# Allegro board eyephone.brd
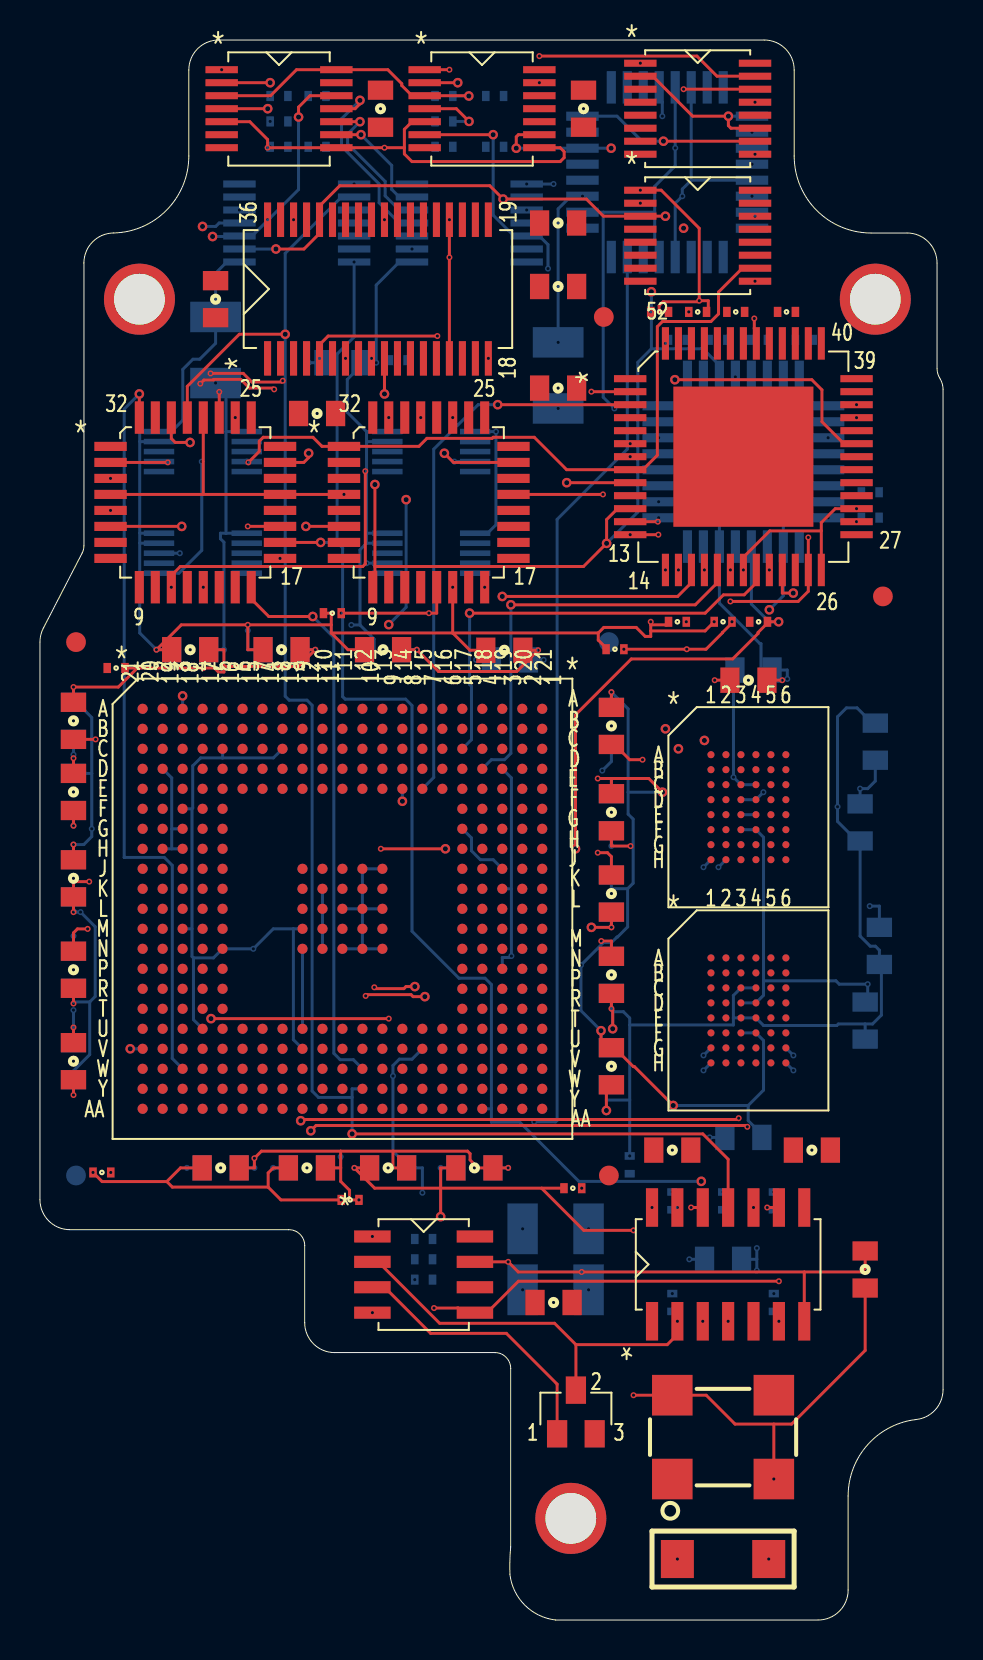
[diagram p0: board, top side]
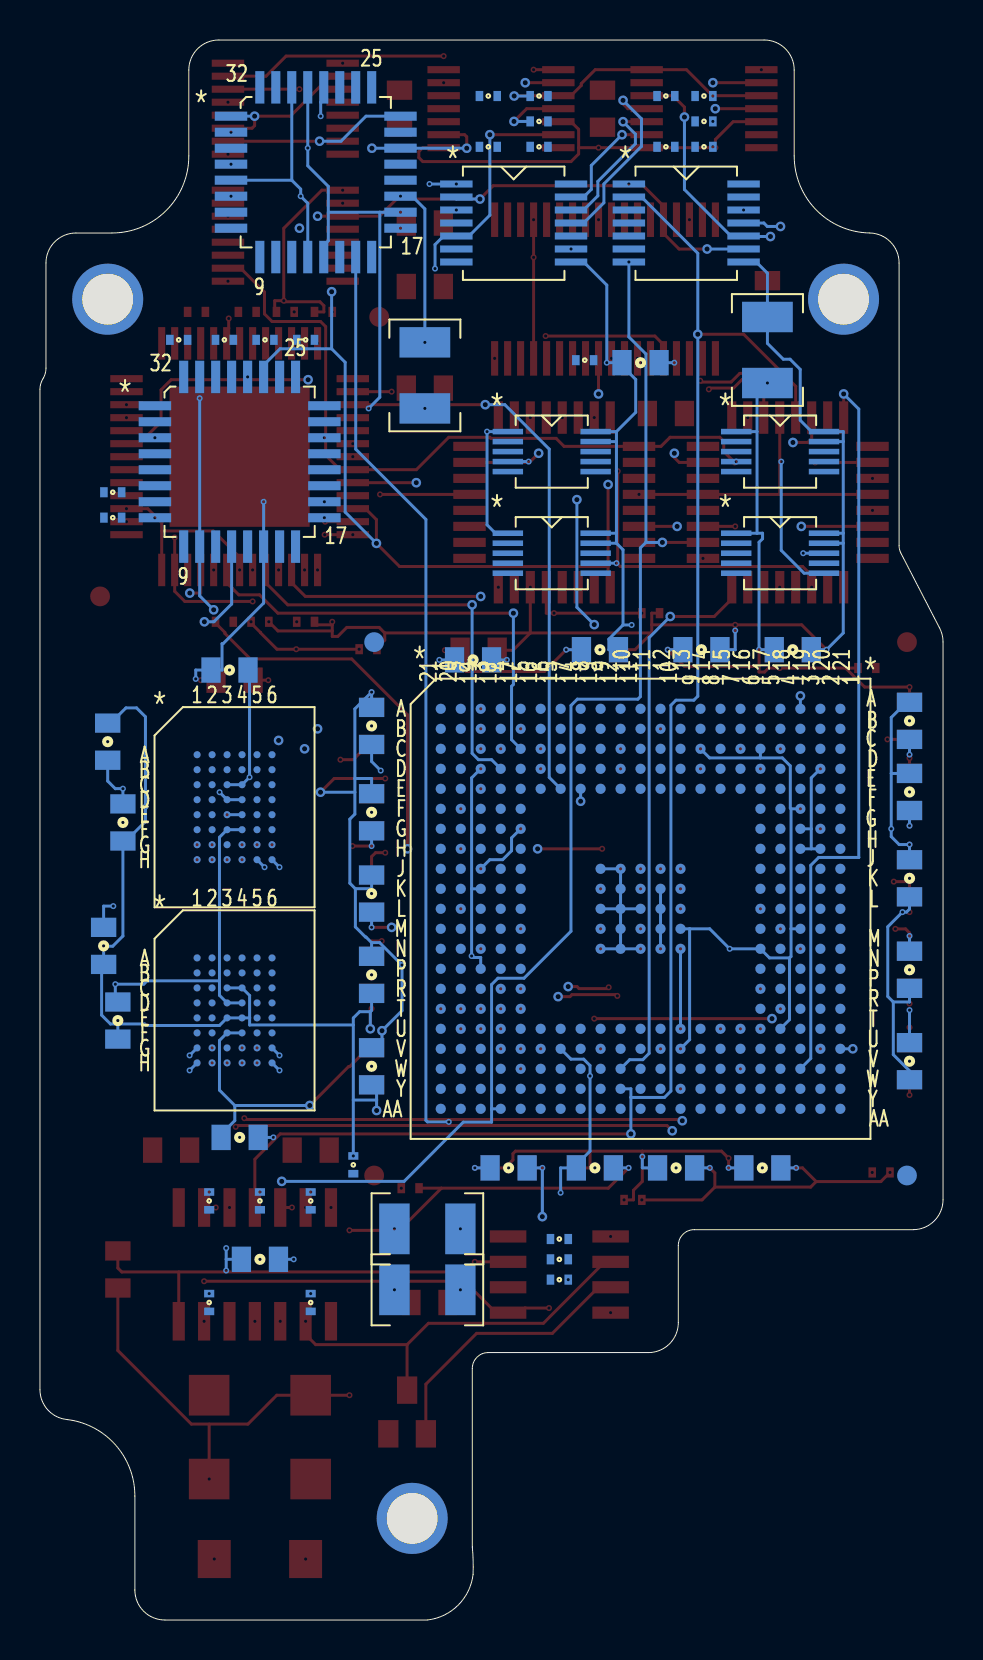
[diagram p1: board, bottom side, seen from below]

Outline 45.2 x 79 mm; copper layers: TOP, GND, VCC, BOTTOM. Coordinates in mm from the lower left corner of the outline.
Outline path: 0,48.9 0,21.02 arc(0.44,19.96) 1.5,19.52 12.46,19.52 arc(13.02,19.28) 13.25,18.73 13.25,14.87 arc(13.69,13.81) 14.75,13.37 22.77,13.37 arc(23.33,13.14) 23.56,12.58 23.56,3.65 arc(23.52,2.97) 23.52,2.29 arc(24.27,0.74) 25.81,0 38.95,0 arc(40.01,0.44) 40.45,1.5 40.45,6.2 arc(41.43,8.77) 43.87,10.03 arc(44.82,10.52) 45.2,11.52 45.2,61.54 arc(45.16,61.81) 45.05,62.06 arc(44.94,62.32) 44.9,62.59 44.9,67.85 arc(44.46,68.91) 43.4,69.35 41.6,69.35 arc(38.88,70.48) 37.75,73.2 37.75,77.5 arc(37.31,78.56) 36.25,79 8.95,79 arc(7.89,78.56) 7.45,77.5 7.45,73.2 arc(6.35,70.5) 3.67,69.35 arc(2.63,68.9) 2.2,67.85 2.2,53.71 arc(2.18,53.52) 2.11,53.35 0.17,49.59 arc(0.04,49.26) 0,48.9

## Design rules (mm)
net group DP1: nets PECL1_N PECL1_P
net group DP2: nets PECL2_N PECL2_P
net group ADDR_BUS: nets ADDR0 ADDR1 ADDR2 ADDR3 ADDR4 ADDR5 ADDR6 ADDR7 ADDR8 ADDR9 ADDR10

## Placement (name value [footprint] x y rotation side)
C1  120PF  [SMC0805]  28.6 32.26 90 top
C2  120PF  [SMC0805]  1.68 44.96 90 top
C3  120PF  [SMC0805]  1.68 41.4 90 top
C4  120PF  [SMC0805]  1.68 37.08 90 top
C5  120PF  [SMC0805]  1.68 27.94 90 top
C6  120PF  [SMC0805]  1.68 32.51 90 top
C7  120PF  [SMC0805]  17.17 48.51 0 top
C8  120PF  [SMC0805]  28.6 44.7 90 top
C9  120PF  [SMC0805]  28.6 40.39 90 top
C10  120PF  [SMC0805]  28.6 36.32 90 top
C11  120PF  [SMC0805]  28.6 27.69 90 top
C12  120PF  [SMC0805]  23.24 48.49 0 top
C13  120PF  [SMC0805]  9.04 22.61 0 top
C14  120PF  [SMC0805]  13.36 22.61 0 top
C15  120PF  [SMC0805]  17.43 22.61 0 top
C16  120PF  [SMC0805]  21.74 22.61 0 top
C17  120PF  [SMC0805]  35.46 46.99 0 top
C18  120PF  [SMC0805]  41.3 17.53 90 top
C19  120PF  [SMC0805]  7.52 48.51 0 top
C20  120PF  [SMC0805]  12.09 48.51 0 top
C21  120PF  [SMC0805]  1.68 37.08 90 bottom
C22  120PF  [SMC0805]  1.68 32.51 90 bottom
C23  120PF  [SMC0805]  12.09 48.51 0 bottom
C24  120PF  [SMC0805]  1.68 27.94 90 bottom
C25  120PF  [SMC0805]  9.04 22.61 0 bottom
C26  120PF  [SMC0805]  17.17 48.51 0 bottom
C27  120PF  [SMC0805]  23.52 48.01 0 bottom
C28  120PF  [SMC0805]  28.6 44.7 90 bottom
C29  120PF  [SMC0805]  28.6 40.39 90 bottom
C30  120PF  [SMC0805]  28.6 36.32 90 bottom
C31  120PF  [SMC0805]  28.6 32.26 90 bottom
C32  120PF  [SMC0805]  7.52 48.51 0 bottom
C33  120PF  [SMC0805]  17.43 22.61 0 bottom
C34  120PF  [SMC0805]  13.36 22.61 0 bottom
C35  120PF  [SMC0805]  21.74 22.61 0 bottom
C36  120PF  [SMC0805]  28.6 27.69 90 bottom
C37  120PF  [SMC0805]  35.21 24.13 0 bottom
C38  120PF  [SMC0805]  35.71 47.5 0 bottom
C39  120PF  [SMC0805]  1.68 41.4 90 bottom
C40  120PF  [SMC0805]  1.68 44.96 90 bottom
C41  10uF  [1210RF]  8.79 63.5 270 bottom
C42  10uF  [1210RF]  25.93 62.23 270 bottom
C43  10uF  [1210RF]  25.81 16.51 180 bottom
C44  10uF  [1210RF]  25.81 19.56 180 bottom
C45  120PF  [SMC0805]  15.14 62.87 180 bottom
C46  120PF  [SMC0805]  41.3 29.97 90 bottom
C47  120PF  [SMC0805]  42.01 33.71 90 bottom
C48  120PF  [SMC0805]  41.81 43.92 270 bottom
C49  120PF  [SMC0805]  41.05 39.88 90 bottom
C50  120PF  [SMC0805]  34.19 18.03 180 bottom
C51  .1UF  [R_0402]  3.81 47.6 0 top
C52  .1UF  [R_0402]  14.63 50.34 0 top
C53  .1UF  [R_0402]  3.1 22.38 0 top
C54  .1UF  [R_0402]  28.78 48.54 0 top
C55  .1UF  [R_0402]  15.52 21.01 0 top
C56  .1UF  [R_0402]  26.67 21.59 0 top
C57  .1UF  [R_0402]  31.01 65.41 0 top
C58  .1UF  [R_0402]  32.92 65.41 0 top
C59  .1UF  [R_0402]  34.19 49.91 0 top
C60  .1UF  [R_0402]  31.9 49.91 0 top
C61  120PF  [SMC0805]  25.93 66.67 0 top
C62  120PF  [SMC0805]  38.63 23.5 0 top
C63  120PF  [SMC0805]  8.79 66.04 90 top
C64  120PF  [SMC0805]  25.93 69.85 0 top
C65  120PF  [SMC0805]  17.04 75.56 90 top
C66  120PF  [SMC0805]  27.2 75.56 90 top
C67  120PF  [SMC0805]  31.65 23.5 0 top
C68  120PF  [SMC0805]  25.71 15.88 0 top
C69  120PF  [SMC0805]  25.93 61.59 0 top
C70  120PF  [SMC0805]  13.87 60.33 0 top
D1  -  [SOT23_132]  26.82 10.41 0 top
D2  V  [SMF1806]  34.19 3.05 180 top
NOREF  -  [unnamed]  26.57 5.08 0 top
NOREF#2  -  [unnamed]  4.98 66.04 0 top
NOREF#3  -  [unnamed]  41.81 66.04 0 top
R1  10K  [R_0402]  34.82 65.41 0 top
R2  10K  [R_0402]  37.36 65.41 0 top
R3  10K  [R_0402]  31.9 64.01 180 bottom
R4  10K  [R_0402]  33.94 64.01 180 bottom
R5  10K  [R_0402]  35.97 64.01 180 bottom
R6  10K  [R_0402]  38.25 64.01 180 bottom
R7  10K  [R_0402]  17.93 62.99 180 bottom
R8  10K  [R_0402]  22.76 73.66 180 bottom
R9  10K  [R_0402]  13.87 76.2 180 bottom
R10  10K  [R_0402]  13.87 73.66 180 bottom
R11  10K  [R_0402]  35.97 49.91 0 top
R12  10K  [R_0402]  22.76 76.2 180 bottom
R13  10K  [R_0402]  20.22 76.2 180 bottom
R14  10K  [R_0402]  11.96 73.66 180 bottom
R15  10K  [R_0402]  11.96 76.2 180 bottom
R16  10K  [R_0402]  11.96 74.93 180 bottom
R17  10K  [R_0402]  20.22 74.93 180 bottom
R18  10K  [R_0402]  20.22 73.66 180 bottom
R19  10K  [R_0402]  41.56 56.39 180 bottom
R20  10K  [R_0402]  19.2 18.03 180 bottom
R21  10K  [R_0402]  19.2 19.05 180 bottom
R22  10K  [R_0402]  19.2 17.02 180 bottom
R23  10K  [R_0402]  41.56 55.12 180 bottom
R24  10K  [R_0402]  29.52 22.76 90 bottom
R25  10K  [R_0402]  31.65 20.95 90 bottom
R26  10K  [R_0402]  36.73 15.88 90 bottom
R27  10K  [R_0402]  34.19 20.95 90 bottom
R28  10K  [R_0402]  31.65 15.88 90 bottom
R29  10K  [R_0402]  36.73 20.95 90 bottom
U1  -  [TSSOP14_26CC_BD4-4MM]  11.96 75.56 0 top
U2  -  [TSSOP14_26CC_BD4-4MM]  22.12 75.56 0 top
U3  -  [TSSOP14_26CC_BD4-4MM]  12.85 69.85 180 bottom
U4  -  [TSSOP14_26CC_BD4-4MM]  21.49 69.85 180 bottom
U5  -  [BGA345_BD23X23MM]  15.14 35.56 0 top
U6  -  [BGA345_BD23X23MM]  15.14 35.56 180 bottom
U7  -  [BGA48_BD7-5X9-5MM]  35.46 40.64 0 top
U8  -  [BGA48_BD7-5X9-5MM]  35.46 30.48 0 top
U9  -  [BGA48_BD7-5X9-5MM]  35.46 40.64 180 bottom
U10  -  [BGA48_BD7-5X9-5MM]  35.46 30.48 180 bottom
U11  -  [SO14NB]  34.44 17.78 90 top
U12  -  [TQFP52_BD10X10MM_THERM]  35.21 58.17 0 top
U13  -  [SSOP36_26CC_BD5-3MM]  16.92 66.55 90 top
U14  -  [SO8NB_V2]  19.2 17.27 0 top
U15  -  [TSSOP16_26CC_BD4-4MM]  32.92 69.22 0 top
U16  -  [TSSOP16_26CC_BD4-4MM]  32.92 75.56 0 top
U17  -  [TQFP32_32CC_BD7X7MM]  7.77 55.88 0 top
U18  -  [TQFP32_32CC_BD7X7MM]  19.46 55.88 0 top
U19  -  [TQFP32_32CC_BD7X7MM]  35.21 57.91 180 bottom
U20  -  [TQFP32_32CC_BD7X7MM]  31.4 72.39 180 bottom
U21  -  [MSOP10_20CC_BD3MM]  8.15 58.42 180 bottom
U22  -  [MSOP10_20CC_BD3MM]  8.15 53.34 180 bottom
U23  -  [MSOP10_20CC_BD3MM]  19.58 58.42 180 bottom
U24  -  [MSOP10_20CC_BD3MM]  19.58 53.34 180 bottom
Y1  -  [4CERAMIC]  34.19 9.14 90 top

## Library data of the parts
C1-C40 C45-C50 C61-C70 = CAP: Tolerance: 5%; alternate symbols: (VSMC0805L,VSMC0805R,VSMC0805B,SMC0805); part number: CAP_805-120PF,5%,50V,805; signal model: capacitor120pF; tolerance: 5%
C41-C44 = CAP: Tolerance: +80-20%; User Part Number: 110-1925-01; alternate symbols: (1210RF_WVI_10P;1210RF_V12P;1210WS;1210WS_WVI_10P); part number: CAP_SMT1210-110-1925-01,10UF,+80-20%,16V; tolerance: +80-20%
C51-C60 = CAP: alternate symbols: (VSMC0603L,VSMC0603R,VSMC0603B,SMC0603); part number: CAP_402-.1UF,&10%,80%,6.3V; signal model: capacitor0pF; tolerance: 10%
D1 = RCNET: User Part Number: 120-3831-01; Tolerance: 10%; part number: RCNET_SOT23-120-3831-01,CTXS03,50,46.4,50,150PF,10%; tolerance: 10%
D2 = BEAD_1806: Tolerance: T; User Part Number: P; part number: BEAD_1806_SMF1806-FBMH4516,TAIYO_FERRITE_BEAD,6A
R1-R29 = RES: alternate symbols: (VSMR0402B,VSMR0402R,VSMR0402L,0402); part number: RES_402-10K,1%,0402; signal model: resistor10K; tolerance: 1%
U1-U4 = LVC07: User Part Number: 100-7328-01; Tolerance: ***; part number: LVC07_TSSOP-100-7328-01,APW
U5 U6 = TALON: User Part Number: 528-1123-01; Tolerance: ***; alternate symbols: (BGA345_BD23X23MM_NF); part number: TALON_BGA345-528-1123-01
U7-U10 = SRAM1MX16: User Part Number: 102-0026-01; Tolerance: ***; part number: SRAM1MX16_BGA-102-0026-01,55NS,K6F1616U6A-EF55
U11 = LVC00: User Part Number: 100-4554-01; Tolerance: ***; part number: LVC00_SO-100-4554-01
U12 = MC100ES6220: Tolerance: ***; User Part Number: 103-0009-01; alternate symbols: (TQFP52_BD10X10MM_THERM_NF); part number: MC100ES6220_TQFP-103-0009-01
U13 = LTC3731: User Part Number: 104-0019-01; Tolerance: ***; part number: LTC3731_SSOP36-104-0019-01
U14 = EEPROM8KX8: Tolerance: ***; User Part Number: 101-0054-01; part number: EEPROM8KX8_SO8-101-0054-01,M34D64
U15 U16 = PCA9554: User Part Number: 100-7579-01; Tolerance: ***; part number: PCA9554_TSSOP-100-7579-01
U17-U20 = CY2HH8110: Tolerance: ***; User Part Number: 100-7829-01; part number: CY2HH8110_TQFP-100-7829-01
U21-U24 = MAX1343: User Part Number: 104-0099-01; Tolerance: ***; part number: MAX1343_MSOP-104-0099-01,10BITADC
Y1 = OSC: part number: OSC_CERAMIC-66.00MHZ,CLOCKING,SG8002JF

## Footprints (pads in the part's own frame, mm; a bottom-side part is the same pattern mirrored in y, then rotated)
4CERAMIC
  rect 2.032x2.032 smd: 1(-2.095,2.54) 2(-2.095,-2.54) 3(2.095,-2.54) 4(2.095,2.54)
1210RF
  rect 1.524x2.54 smd: 1(-1.651,0) 2(1.651,0)
BGA48_BD7-5X9-5MM
  round 0.356 smd: A1(-1.875,2.625) A2(-1.125,2.625) A3(-0.375,2.625) A4(0.375,2.625) A5(1.125,2.625) A6(1.875,2.625) B1(-1.875,1.875) B2(-1.125,1.875) B3(-0.375,1.875) B4(0.375,1.875) B5(1.125,1.875) B6(1.875,1.875) C1(-1.875,1.125) C2(-1.125,1.125) C3(-0.375,1.125) C4(0.375,1.125) C5(1.125,1.125) C6(1.875,1.125) D1(-1.875,0.375) D2(-1.125,0.375) D3(-0.375,0.375) D4(0.375,0.375) D5(1.125,0.375) D6(1.875,0.375) E1(-1.875,-0.375) E2(-1.125,-0.375) E3(-0.375,-0.375) E4(0.375,-0.375) E5(1.125,-0.375) E6(1.875,-0.375) F1(-1.875,-1.125) F2(-1.125,-1.125) F3(-0.375,-1.125) F4(0.375,-1.125) F5(1.125,-1.125) F6(1.875,-1.125) G1(-1.875,-1.875) G2(-1.125,-1.875) G3(-0.375,-1.875) G4(0.375,-1.875) G5(1.125,-1.875) G6(1.875,-1.875) H1(-1.875,-2.625) H2(-1.125,-2.625) H3(-0.375,-2.625) H4(0.375,-2.625) H5(1.125,-2.625) H6(1.875,-2.625)
BGA345_BD23X23MM
  round 0.991 smd: (-13.335,13.335) (13.335,-13.335)
  round 0.508 smd: A1(-10,10) A2(-9,10) A3(-8,10) A4(-7,10) A5(-6,10) A6(-5,10) A7(-4,10) A8(-3,10) A9(-2,10) A10(-1,10) A11(0,10) A12(1,10) A13(2,10) A14(3,10) A15(4,10) A16(5,10) A17(6,10) A18(7,10) A19(8,10) A20(9,10) A21(10,10) AA1(-10,-10) AA2(-9,-10) AA3(-8,-10) AA4(-7,-10) AA5(-6,-10) AA6(-5,-10) AA7(-4,-10) AA8(-3,-10) AA9(-2,-10) AA10(-1,-10) AA11(0,-10) AA12(1,-10) AA13(2,-10) AA14(3,-10) AA15(4,-10) AA16(5,-10) AA17(6,-10) AA18(7,-10) AA19(8,-10) AA20(9,-10) AA21(10,-10) B1(-10,9) B2(-9,9) B3(-8,9) B4(-7,9) B5(-6,9) B6(-5,9) B7(-4,9) B8(-3,9) B9(-2,9) B10(-1,9) B11(0,9) B12(1,9) B13(2,9) B14(3,9) B15(4,9) B16(5,9) B17(6,9) B18(7,9) B19(8,9) B20(9,9) B21(10,9) C1(-10,8) C2(-9,8) C3(-8,8) C4(-7,8) C5(-6,8) C6(-5,8) C7(-4,8) C8(-3,8) C9(-2,8) C10(-1,8) C11(0,8) C12(1,8) C13(2,8) C14(3,8) C15(4,8) C16(5,8) C17(6,8) C18(7,8) C19(8,8) C20(9,8) C21(10,8) D1(-10,7) D2(-9,7) D3(-8,7) D4(-7,7) D5(-6,7) D6(-5,7) D7(-4,7) D8(-3,7) D9(-2,7) D10(-1,7) D11(0,7) D12(1,7) D13(2,7) D14(3,7) D15(4,7) D16(5,7) D17(6,7) D18(7,7) D19(8,7) D20(9,7) D21(10,7) E1(-10,6) E2(-9,6) E3(-8,6) E4(-7,6) E5(-6,6) E6(-5,6) E7(-4,6) E8(-3,6) E9(-2,6) E10(-1,6) E11(0,6) E12(1,6) E13(2,6) E14(3,6) E15(4,6) E16(5,6) E17(6,6) E18(7,6) E19(8,6) E20(9,6) E21(10,6) F1(-10,5) F2(-9,5) F3(-8,5) F4(-7,5) F5(-6,5) F17(6,5) F18(7,5) F19(8,5) F20(9,5) F21(10,5) G1(-10,4) G2(-9,4) G3(-8,4) G4(-7,4) G5(-6,4) G17(6,4) G18(7,4) G19(8,4) G20(9,4) G21(10,4) H1(-10,3) H2(-9,3) H3(-8,3) H4(-7,3) H5(-6,3) H17(6,3) H18(7,3) H19(8,3) H20(9,3) H21(10,3) J1(-10,2) J2(-9,2) J3(-8,2) J4(-7,2) J5(-6,2) J9(-2,2) J10(-1,2) J11(0,2) J12(1,2) J13(2,2) J17(6,2) J18(7,2) J19(8,2) J20(9,2) J21(10,2) K1(-10,1) K2(-9,1) K3(-8,1) K4(-7,1) K5(-6,1) K9(-2,1) K10(-1,1) K11(0,1) K12(1,1) K13(2,1) K17(6,1) K18(7,1) K19(8,1) K20(9,1) K21(10,1) L1(-10,0) L2(-9,0) L3(-8,0) L4(-7,0) L5(-6,0) L9(-2,0) L10(-1,0) L11(0,0) L12(1,0) L13(2,0) L17(6,0) L18(7,0) L19(8,0) L20(9,0) L21(10,0) M1(-10,-1) M2(-9,-1) M3(-8,-1) M4(-7,-1) M5(-6,-1) M9(-2,-1) M10(-1,-1) M11(0,-1) M12(1,-1) M13(2,-1) M17(6,-1) M18(7,-1) M19(8,-1) M20(9,-1) M21(10,-1) N1(-10,-2) N2(-9,-2) N3(-8,-2) N4(-7,-2) N5(-6,-2) N9(-2,-2) N10(-1,-2) N11(0,-2) N12(1,-2) N13(2,-2) N17(6,-2) N18(7,-2) N19(8,-2) N20(9,-2) N21(10,-2) P1(-10,-3) P2(-9,-3) P3(-8,-3) P4(-7,-3) P5(-6,-3) P17(6,-3) P18(7,-3) P19(8,-3) P20(9,-3) P21(10,-3) R1(-10,-4) R2(-9,-4) R3(-8,-4) R4(-7,-4) R5(-6,-4) R17(6,-4) R18(7,-4) R19(8,-4) R20(9,-4) R21(10,-4) T1(-10,-5) T2(-9,-5) T3(-8,-5) T4(-7,-5) T5(-6,-5) T17(6,-5) T18(7,-5) T19(8,-5) T20(9,-5) T21(10,-5) U1(-10,-6) U2(-9,-6) U3(-8,-6) U4(-7,-6) U5(-6,-6) U6(-5,-6) U7(-4,-6) U8(-3,-6) U9(-2,-6) U10(-1,-6) U11(0,-6) U12(1,-6) U13(2,-6) U14(3,-6) U15(4,-6) U16(5,-6) U17(6,-6) U18(7,-6) U19(8,-6) U20(9,-6) U21(10,-6) V1(-10,-7) V2(-9,-7) V3(-8,-7) V4(-7,-7) V5(-6,-7) V6(-5,-7) V7(-4,-7) V8(-3,-7) V9(-2,-7) V10(-1,-7) V11(0,-7) V12(1,-7) V13(2,-7) V14(3,-7) V15(4,-7) V16(5,-7) V17(6,-7) V18(7,-7) V19(8,-7) V20(9,-7) V21(10,-7) W1(-10,-8) W2(-9,-8) W3(-8,-8) W4(-7,-8) W5(-6,-8) W6(-5,-8) W7(-4,-8) W8(-3,-8) W9(-2,-8) W10(-1,-8) W11(0,-8) W12(1,-8) W13(2,-8) W14(3,-8) W15(4,-8) W16(5,-8) W17(6,-8) W18(7,-8) W19(8,-8) W20(9,-8) W21(10,-8) Y1(-10,-9) Y2(-9,-9) Y3(-8,-9) Y4(-7,-9) Y5(-6,-9) Y6(-5,-9) Y7(-4,-9) Y8(-3,-9) Y9(-2,-9) Y10(-1,-9) Y11(0,-9) Y12(1,-9) Y13(2,-9) Y14(3,-9) Y15(4,-9) Y16(5,-9) Y17(6,-9) Y18(7,-9) Y19(8,-9) Y20(9,-9) Y21(10,-9)
MSOP10_20CC_BD3MM
  rect 1.524x0.279 smd: 1(-2.197,1) 2(-2.197,0.5) 3(-2.197,0) 4(-2.197,-0.5) 5(-2.197,-1) 6(2.197,-1) 7(2.197,-0.5) 8(2.197,0) 9(2.197,0.5) 10(2.197,1)
R_0402
  rect 0.381x0.508 smd: 1(-0.445,0) 2(0.445,0)
SMC0805
  rect 0.965x1.27 smd: 1(-0.927,0) 2(0.927,0)
SMF1806
  rect 1.651x1.905 smd: 1(-2.286,0) 2(2.286,0)
SO8NB_V2
  rect 1.829x0.61 smd: 1(-2.565,1.905) 2(-2.565,0.635) 3(-2.565,-0.635) 4(-2.565,-1.905) 5(2.565,-1.905) 6(2.565,-0.635) 7(2.565,0.635) 8(2.565,1.905)
SO14NB
  rect 1.93x0.61 smd: 1(-2.845,3.81) 2(-2.845,2.54) 3(-2.845,1.27) 4(-2.845,0) 5(-2.845,-1.27) 6(-2.845,-2.54) 7(-2.845,-3.81) 8(2.845,-3.81) 9(2.845,-2.54) 10(2.845,-1.27) 11(2.845,0) 12(2.845,1.27) 13(2.845,2.54) 14(2.845,3.81)
SOT23_132
  rect 1.016x1.372 smd: 1(-0.94,-1.105) 2(0,1.079) 3(0.94,-1.105)
SSOP36_26CC_BD5-3MM
  rect 1.727x0.356 smd: 1(-3.467,5.525) 2(-3.467,4.875) 3(-3.467,4.225) 4(-3.467,3.575) 5(-3.467,2.925) 6(-3.467,2.275) 7(-3.467,1.625) 8(-3.467,0.975) 9(-3.467,0.325) 10(-3.467,-0.325) 11(-3.467,-0.975) 12(-3.467,-1.625) 13(-3.467,-2.275) 14(-3.467,-2.925) 15(-3.467,-3.575) 16(-3.467,-4.225) 17(-3.467,-4.875) 18(-3.467,-5.525) 19(3.467,-5.525) 20(3.467,-4.875) 21(3.467,-4.225) 22(3.467,-3.575) 23(3.467,-2.925) 24(3.467,-2.275) 25(3.467,-1.625) 26(3.467,-0.975) 27(3.467,-0.325) 28(3.467,0.325) 29(3.467,0.975) 30(3.467,1.625) 31(3.467,2.275) 32(3.467,2.925) 33(3.467,3.575) 34(3.467,4.225) 35(3.467,4.875) 36(3.467,5.525)
TQFP32_32CC_BD7X7MM
  rect 1.626x0.457 smd: 1(-4.242,2.8) 2(-4.242,2) 3(-4.242,1.2) 4(-4.242,0.4) 5(-4.242,-0.4) 6(-4.242,-1.2) 7(-4.242,-2) 8(-4.242,-2.8) 17(4.242,-2.8) 18(4.242,-2) 19(4.242,-1.2) 20(4.242,-0.4) 21(4.242,0.4) 22(4.242,1.2) 23(4.242,2) 24(4.242,2.8)
  rect 0.457x1.626 smd: 9(-2.8,-4.242) 10(-2,-4.242) 11(-1.2,-4.242) 12(-0.4,-4.242) 13(0.4,-4.242) 14(1.2,-4.242) 15(2,-4.242) 16(2.8,-4.242) 25(2.8,4.242) 26(2,4.242) 27(1.2,4.242) 28(0.4,4.242) 29(-0.4,4.242) 30(-1.2,4.242) 31(-2,4.242) 32(-2.8,4.242)
TQFP52_BD10X10MM_THERM
  round 0.991 smd: (-6.985,6.985) (6.985,-6.985)
  rect 1.626x0.356 smd: 1(-5.664,3.9) 2(-5.664,3.25) 3(-5.664,2.6) 4(-5.664,1.95) 5(-5.664,1.3) 6(-5.664,0.65) 7(-5.664,0) 8(-5.664,-0.65) 9(-5.664,-1.3) 10(-5.664,-1.95) 11(-5.664,-2.6) 12(-5.664,-3.25) 13(-5.664,-3.9) 27(5.664,-3.9) 28(5.664,-3.25) 29(5.664,-2.6) 30(5.664,-1.95) 31(5.664,-1.3) 32(5.664,-0.65) 33(5.664,0) 34(5.664,0.65) 35(5.664,1.3) 36(5.664,1.95) 37(5.664,2.6) 38(5.664,3.25) 39(5.664,3.9)
  rect 0.356x1.626 smd: 14(-3.9,-5.664) 15(-3.25,-5.664) 16(-2.6,-5.664) 17(-1.95,-5.664) 18(-1.3,-5.664) 19(-0.65,-5.664) 20(0,-5.664) 21(0.65,-5.664) 22(1.3,-5.664) 23(1.95,-5.664) 24(2.6,-5.664) 25(3.25,-5.664) 26(3.9,-5.664) 40(3.9,5.664) 41(3.25,5.664) 42(2.6,5.664) 43(1.95,5.664) 44(1.3,5.664) 45(0.65,5.664) 46(0,5.664) 47(-0.65,5.664) 48(-1.3,5.664) 49(-1.95,5.664) 50(-2.6,5.664) 51(-3.25,5.664) 52(-3.9,5.664)
TSSOP14_26CC_BD4-4MM
  rect 1.626x0.356 smd: 1(-2.87,1.95) 2(-2.87,1.3) 3(-2.87,0.65) 4(-2.87,0) 5(-2.87,-0.65) 6(-2.87,-1.3) 7(-2.87,-1.95) 8(2.87,-1.95) 9(2.87,-1.3) 10(2.87,-0.65) 11(2.87,0) 12(2.87,0.65) 13(2.87,1.3) 14(2.87,1.95)
TSSOP16_26CC_BD4-4MM
  rect 1.626x0.356 smd: 1(-2.87,2.275) 2(-2.87,1.625) 3(-2.87,0.975) 4(-2.87,0.325) 5(-2.87,-0.325) 6(-2.87,-0.975) 7(-2.87,-1.625) 8(-2.87,-2.275) 9(2.87,-2.275) 10(2.87,-1.625) 11(2.87,-0.975) 12(2.87,-0.325) 13(2.87,0.325) 14(2.87,0.975) 15(2.87,1.625) 16(2.87,2.275)
unnamed
  round 3.556 hole 2.54 unplated: (0,0)

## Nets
GND: C1.2(B<0>) C2.2(B<0>) C3.2(B<0>) C4.2(B<0>) C5.2(B<0>) C6.2(B<0>) C7.2(B<0>) C8.2(B<0>) C9.2(B<0>) C10.2(B<0>) C11.2(B<0>) C12.2(B<0>) C13.2(B<0>) C14.2(B<0>) C15.2(B<0>) C16.2(B<0>) C17.2(B<0>) C18.2(B<0>) C19.2(B<0>) C20.2(B<0>) C21.2(B<0>) C22.2(B<0>) C23.2(B<0>) C24.2(B<0>) C25.2(B<0>) C26.2(B<0>) C27.2(B<0>) C28.2(B<0>) C29.2(B<0>) C30.2(B<0>) C31.2(B<0>) C32.2(B<0>) C33.2(B<0>) C34.2(B<0>) C35.2(B<0>) C36.2(B<0>) C37.2(B<0>) C38.2(B<0>) C39.2(B<0>) C40.2(B<0>) C41.2(B<0>) C42.2(B<0>) C43.1(A<0>) C44.1(A<0>) C45.2(B<0>) C46.2(B<0>) C47.2(B<0>) C48.2(B<0>) C49.2(B<0>) C50.2(B<0>) C51.2(B<0>) C52.2(B<0>) C53.2(B<0>) C54.2(B<0>) C55.2(B<0>) C56.2(B<0>) C57.2(B<0>) C58.2(B<0>) C59.2(B<0>) C60.2(B<0>) U1.1(A<1>) U2.1(A<1>) U3.1(A<1>) U4.1(A<1>) U6.C6(PCI_AD_28_SRAM_DATA_10) U6.C10(PCI_IDSEL_SRAM_CS2_FB_N) U6.C14(PCI_AD_SRAM_ADDR<18>) U6.C17(PCI_PAR_SRAM_DATA_4) U6.D3(SB_MASTER_IN_N<16>) U6.F19(MODE<1>) U6.G20(V3_3<7>) U6.K3(SB_MASTER_OUT_N<17>) U6.K9(VSS<38>) U6.K11(VSS<36>) U6.K13(VSS<34>) U6.M9(VSS<26>) U6.M11(VSS<24>) U6.M13(VSS<22>) U6.M19(JTAG_MTDI) U6.N17(V1_5CORE<4>) U6.P3(SB_MASTER_OUT_N<18>) U6.U18(V3_3<17>) U6.V7(VSS<9>) U6.V13(V1_5<5>) U9.D3(A<17>) U9.D4(A<7>) U9.F3(A<14>) U9.F4(A<15>) U10.D3(A<17>) U10.D4(A<7>) U10.F3(A<14>) U10.F4(A<15>) U11.7(GND) U12.7(CLKB) U12.13(QB<8>) U12.20(QB<5>) U12.26(QB<2>) U12.29(QB<1>) U12.36(QA_N<7>) U12.45(QA_N<3>) U12.52(QA<0>) U13.7(DIFFOUT) U13.15(SENSE3) U13.22(TG3) U13.34(BOOST1) U14.1(E<0>) U14.7(WC_N) U15.1(A0) U16.1(A0) U17.4(OE_N) U17.13(VDD<4>) U17.21(VDD<6>) U17.28(VDD<7>) U18.4(OE_N) U18.13(VDD<4>) U18.21(VDD<6>) U18.29(VDD<8>) U19.3(VDD<1>) U19.14(Q<9>) U19.18(Q<7>) U19.22(Q<5>) U19.28(VDD<7>) U20.4(OE_N) U20.13(VDD<4>) U20.18(Q<7>) U20.29(VDD<8>) U21.1(AIN0) U22.1(AIN0) U23.1(AIN0) U24.1(AIN0)
VCC: C1.1(A<0>) C2.1(A<0>) C3.1(A<0>) C4.1(A<0>) C5.1(A<0>) C6.1(A<0>) C7.1(A<0>) C8.1(A<0>) C9.1(A<0>) C10.1(A<0>) C11.1(A<0>) C12.1(A<0>) C13.1(A<0>) C14.1(A<0>) C15.1(A<0>) C16.1(A<0>) C17.1(A<0>) C18.1(A<0>) C19.1(A<0>) C20.1(A<0>) C21.1(A<0>) C22.1(A<0>) C23.1(A<0>) C24.1(A<0>) C25.1(A<0>) C26.1(A<0>) C27.1(A<0>) C28.1(A<0>) C29.1(A<0>) C30.1(A<0>) C31.1(A<0>) C32.1(A<0>) C33.1(A<0>) C34.1(A<0>) C35.1(A<0>) C36.1(A<0>) C37.1(A<0>) C38.1(A<0>) C39.1(A<0>) C40.1(A<0>) C41.1(A<0>) C42.1(A<0>) C43.2(B<0>) C44.2(B<0>) C45.1(A<0>) C46.1(A<0>) C47.1(A<0>) C48.1(A<0>) C49.1(A<0>) C50.1(A<0>) C51.1(A<0>) C52.1(A<0>) C53.1(A<0>) C54.1(A<0>) C55.1(A<0>) C56.1(A<0>) C57.1(A<0>) C58.1(A<0>) C59.1(A<0>) C60.1(A<0>) D2.1(A) R22.2(B<0>) R23.2(B<0>) R24.2(B<0>) R25.2(B<0>) R26.2(B<0>) R27.2(B<0>) R28.2(B<0>) R29.2(B<0>) U1.5(A<1>) U1.8(Y<1>) U2.5(A<1>) U2.8(Y<1>) U3.8(Y<1>) U4.8(Y<1>) U6.B12(PCI_AD_SRAM_ADDR<12>) U6.C16(PCI_AD_SRAM_ADDR<2>) U6.C18(PCI_AD_SRAM_ADDR<0>) U6.D6(PCI_RST_N_SRAM_WR_FB_N) U6.D10(PCI_GNT_N_SRAM_CS0_FB_N) U6.D14(PCI_AD_SRAM_ADDR<6>) U6.D17(V3_3<8>) U6.D20(I2C_SDA<0>) U6.E3(SB_MASTER_OUT_N<1>) U6.F2(SB_MASTER_OUT_N<2>) U6.G5(TMP_OUT) U6.G19(MODE<2>) U6.H19(MODE<3>) U6.H20(I2C_SDA<2>) U6.J3(SB_MASTER_OUT_N<5>) U6.J9(VSS<44>) U6.J10(VSS<43>) U6.J11(VSS<42>) U6.J12(VSS<41>) U6.J13(VSS<40>) U6.K10(VSS<37>) U6.K12(VSS<35>) U6.L2(V1_5<10>) U6.L9(VSS<32>) U6.L10(VSS<31>) U6.L11(VSS<30>) U6.L12(VSS<29>) U6.L13(VSS<28>) U6.L17(MIT_TEST3) U6.M5(JTAG_TCK_HSTL_SPARE2) U6.M10(VSS<25>) U6.M12(VSS<23>) U6.M18(SRAM_CS1_N) U6.N3(SB_MASTER_OUT_N<9>) U6.N9(VSS<20>) U6.N10(VSS<19>) U6.N11(VSS<18>) U6.N12(VSS<17>) U6.N13(VSS<16>) U6.N19(JTAG_MTDO) U6.R17(MIT_TEST6) U6.T5(FREEZE_N) U6.T18(LVTTL_SPARE_IN<1>) U6.U13(V1_5CORE<1>) U6.U16(LVTTL_SPARE_IN<0>) U6.U17(V1_5CORE<0>) U6.V6(TLN_MONITOR<0>) U6.V12(JTAG_TDO_R<7>) U6.W16(TAP_TRST_N) U9.C3(A<5>) U9.C4(A<6>) U9.E3(VSS<2>) U9.E4(A<16>) U10.C3(A<5>) U10.C4(A<6>) U10.E3(VSS<2>) U10.E4(A<16>) U11.14(VCC) U12.6(VBB) U12.12(QB_N<8>) U12.19(QB_N<5>) U12.25(QB_N<2>) U12.28(QB_N<1>) U12.37(QA<7>) U13.5(IN) U13.18(UVADJ) U13.27(BG1) U13.36(CLKOUT) U15.9(IO4) U15.14(SCL) U16.9(IO4) U16.13(INT_N) U17.5(GND<1>) U17.19(Q<6>) U17.27(Q<2>) U18.14(Q<9>) U18.27(Q<2>) U20.5(GND<1>) U20.12(VDD<3>) U20.19(Q<6>) U20.30(Q<1>) U21.9(GND) U21.10(VDD) U22.9(GND) U22.10(VDD) U23.9(GND) U23.10(VDD) U24.9(GND) U24.10(VDD) Y1.2(GND) Y1.4(VCC)
A1: U6.B3(V3_3<16>) U12.14(VCC3)
A2: U6.C3(VSS<55>) U12.15(QB_N<7>)
A3: U6.A3(VSS<64>) U12.16(QB<7>)
A4: U6.C4(PCI_AD_31_SRAM_DATA_13) U12.17(QB_N<6>)
A5: U6.D4(VSS<54>) U12.18(QB<6>)
A6: U6.C5(PCI_AD_27_SRAM_DATA_9) U12.21(QB_N<4>)
A7: U6.B5(VSS<61>) U12.23(QB_N<3>)
ADDR0: U6.V5(V1_5<7>) U9.H2(A<8>) U10.H2(A<8>)
ADDR1: U6.U2(VSS<12>) U9.H6 U10.H6
ADDR2: U6.T2(SB_MASTER_OUT_N<12>) U9.H5(A<11>) U10.H5(A<11>)
ADDR3: U6.T3(SB_MASTER_IN_N<19>) U9.G6(IO<7>) U10.G6(IO<7>)
ADDR4: U6.U3(SB_MASTER_OUT_N<13>) U9.G5(WE_N) U10.G5(WE_N)
ADDR5: U6.T4(SB_SLAVE_OUT_N<2>) U9.G4(A<13>) U10.G4(A<13>)
ADDR6: U6.U4(SB_SLAVE_IN_N<3>) U9.H4(A<10>) U10.H4(A<10>)
ADDR7: U6.V4(VSS<10>) U9.H3(A<9>) U10.H3(A<9>)
ADDR8: U6.T1(SB_MASTER_IN_N<12>) U9.G2(A<19>) U10.G2(A<19>)
ADDR9: U6.R4(VSS<14>) U9.H1(A<18>) U10.H1(A<18>)
ADDR10: U6.R5(JTAG_TCK_HSTL_SPARE0) U9.G1(IO<15>) U10.G1(IO<15>)
CLK_OUT: Y1.3(CLK)
HDI_STACK: U3.9(A<1>) U4.2(Y<1>) U13.32(SW1) U15.3(A2) U20.6(IN)
NET1: U1.9(A<1>) U4.13(A<1>)
NET2: U1.10(Y<1>) U4.12(Y<1>)
NET3: U1.11(A<1>) U4.11(A<1>)
NET4: U6.A19(PCI_AD_SRAM_ADDR<11>) U12.9(VEE2) U17.6(IN) U18.6(IN)
NET5: D1.2(P2) D2.2(B) U11.2(B<0>) U14.2(E<1>)
NET7: D1.1(P1) U14.3(E<2>)
NET8: R16.2(B<0>) U2.9(A<1>) U12.11(QB<9>) U15.2(A1) U17.30(Q<1>) U18.9(GND<3>) U19.27(Q<2>) U20.22(Q<5>)
NET9: U12.8(CLKB_N) U15.10(IO5) U17.2(GND<0>) U18.1(VDD<0>)
NET11: U2.13(A<1>) U16.15(SDA)
NET12: R14.2(B<0>) U3.12(Y<1>) U4.3(A<1>) U4.9(A<1>) U20.2(GND<0>)
NET13: U12.34(QA_N<8>) U17.23(Q<4>) U18.23(Q<4>)
NET14: U19.8(GND<2>) U21.4(AIN3_VREF) U22.6(INT_N) U23.4(AIN3_VREF)
NET15: U19.17(GND<6>) U22.8(SDA) U24.7(SCL)
NET16: U2.6(Y<1>) U4.5(A<1>) U12.22(QB<4>) U19.10(GND<4>)
NET17: U6.V21(I2C_SCL<7>) U13.9(SGND) U17.11(Q<10>)
NET20: U6.W19(LED0) U13.10(SENSE1) U17.32(GND<10>)
NET21: U6.W10(TLN_ASIC_RST0_N) U17.16(GND<5>)
NET24: U3.7(GND) U6.AA4(JTAG_TDI_R<0>) U11.3(Y_N<0>) U11.4(A<0>) U16.14(SCL) U17.18(Q<7>) U20.17(GND<6>)
NET25: U3.2(Y<1>) U6.Y10(JTAG_TDO_R<3>) U11.11(Y_N<0>) U17.29(VDD<8>)
NET28: U6.V20(I2C_SDA<7>) U11.6(Y_N<0>) U14.5(SDA) U18.31(GND<9>)
NET30: R15.2(B<0>) U1.2(Y<1>) U2.2(Y<1>) U16.2(A1) U16.11(IO6) U20.1(VDD<0>) U20.28(VDD<7>)
NET31: R13.1(A<0>) U1.3(A<1>) U1.14(VCC) U2.3(A<1>)
NET32: R17.1(A<0>) U1.4(Y<1>) U2.4(Y<1>)
NET33: R11.2(B<0>) U6.H2(SB_MASTER_OUT_N<4>) U14.4(VSS) U19.12(VDD<3>)
NET34: U16.10(IO5) U20.24(GND<7>)
PECL1_N: U3.11(A<1>) U6.Y13(VSS<2>) U11.10(B<0>) U17.3(VDD<1>)
PECL1_P: U1.12(Y<1>) U3.10(Y<1>) U6.U15(JTAG_TMS_R<7>) U11.9(A<0>) U17.26(Q<3>)
PECL2_N: U6.V9(V1_5<6>) U11.13(B<0>) U17.17(GND<6>)
PECL2_P: U6.W5(BB_SLAVE_IN0_N) U11.12(A<0>) U18.16(GND<5>) U20.15(Q<8>)
PHASE_N: U6.E7(PCI_AD_SRAM_ADDR<26>) U12.3(VEE1)
PHASE_P: U6.E8(PCI_SPARE5) U12.2(VCC2)

Pads without a net: C61 1 2; C62 1 2; C63 1 2; C64 1 2; C65 1 2; C66 1 2; C67 1 2; C68 1 2; C69 1 2; C70 1 2; D1 3; R1 1 2; R2 1 2; R3 1 2; R4 1 2; R5 1 2; R6 1 2; R7 1 2; R8 1 2; R9 1 2; R10 1 2; R11 1; R12 1 2; R13 2; R14 1; R15 1; R16 1; R17 2; R18 1 2; R19 1 2; R20 1 2; R21 1 2; R22 1; R23 1; R24 1; R25 1; R26 1; R27 1; R28 1; R29 1; U1 6 7 13; U2 7 10 11 12 14; U3 3 4 5 6 13 14; U4 4 6 7 10 14; U5 A1 A2 A3 A4 A5 A6 A7 A8 A9 A10 A11 A12 A13 A14 A15 A16 A17 A18 A19 A20 A21 AA1 AA2 AA3 AA4 AA5 AA6 AA7 AA8 AA9 AA10 AA11 AA12 AA13 AA14 AA15 AA16 AA17 AA18 AA19 AA20 AA21 B1 B2 B3 B4 B5 B6 B7 B8 B9 B10 B11 B12 B13 B14 B15 B16 B17 B18 B19 B20 B21 C1 C2 C3 C4 C5 C6 C7 C8 C9 C10 C11 C12 C13 C14 C15 C16 C17 C18 C19 C20 C21 D1 D2 D3 D4 D5 D6 D7 D8 D9 D10 D11 D12 D13 D14 D15 D16 D17 D18 D19 D20 D21 E1 E2 E3 E4 E5 E6 E7 E8 E9 E10 E11 E12 E13 E14 E15 E16 E17 E18 E19 E20 E21 F1 F2 F3 F4 F5 F17 F18 F19 F20 F21 G1 G2 G3 G4 G5 G17 G18 G19 G20 G21 H1 H2 H3 H4 H5 H17 H18 H19 H20 H21 J1 J2 J3 J4 J5 J9 J10 J11 J12 J13 J17 J18 J19 J20 J21 K1 K2 K3 K4 K5 K9 K10 K11 K12 K13 K17 K18 K19 K20 K21 L1 L2 L3 L4 L5 L9 L10 L11 L12 L13 L17 L18 L19 L20 L21 M1 M2 M3 M4 M5 M9 M10 M11 M12 M13 M17 M18 M19 M20 M21 N1 N2 N3 N4 N5 N9 N10 N11 N12 N13 N17 N18 N19 N20 N21 P1 P2 P3 P4 P5 P17 P18 P19 P20 P21 R1 R2 R3 R4 R5 R17 R18 R19 R20 R21 T1 T2 T3 T4 T5 T17 T18 T19 T20 T21 U1 U2 U3 U4 U5 U6 U7 U8 U9 U10 U11 U12 U13 U14 U15 U16 U17 U18 U19 U20 U21 V1 V2 V3 V4 V5 V6 V7 V8 V9 V10 V11 V12 V13 V14 V15 V16 V17 V18 V19 V20 V21 W1 W2 W3 W4 W5 W6 W7 W8 W9 W10 W11 W12 W13 W14 W15 W16 W17 W18 W19 W20 W21 Y1 Y2 Y3 Y4 Y5 Y6 Y7 Y8 Y9 Y10 Y11 Y12 Y13 Y14 Y15 Y16 Y17 Y18 Y19 Y20 Y21; U6 A1 A2 A4 A5 A6 A7 A8 A9 A10 A11 A12 A13 A14 A15 A16 A17 A18 A20 A21 AA1 AA2 AA3 AA5 AA6 AA7 AA8 AA9 AA10 AA11 AA12 AA13 AA14 AA15 AA16 AA17 AA18 AA19 AA20 AA21 B1 B2 B4 B6 B7 B8 B9 B10 B11 B13 B14 B15 B16 B17 B18 B19 B20 B21 C1 C2 C7 C8 C9 C11 C12 C13 C15 C19 C20 C21 D1 D2 D5 D7 D8 D9 D11 D12 D13 D15 D16 D18 D19 D21 E1 E2 E4 E5 E6 E9 E10 E11 E12 E13 E14 E15 E16 E17 E18 E19 E20 E21 F1 F3 F4 F5 F17 F18 F20 F21 G1 G2 G3 G4 G17 G18 G21 H1 H3 H4 H5 H17 H18 H21 J1 J2 J4 J5 J17 J18 J19 J20 J21 K1 K2 K4 K5 K17 K18 K19 K20 K21 L1 L3 L4 L5 L18 L19 L20 L21 M1 M2 M3 M4 M17 M20 M21 N1 N2 N4 N5 N18 N20 N21 P1 P2 P4 P5 P17 P18 P19 P20 P21 R1 R2 R3 R18 R19 R20 R21 T17 T19 T20 T21 U1 U5 U6 U7 U8 U9 U10 U11 U12 U14 U19 U20 U21 V1 V2 V3 V8 V10 V11 V14 V15 V16 V17 V18 V19 W1 W2 W3 W4 W6 W7 W8 W9 W11 W12 W13 W14 W15 W17 W18 W20 W21 Y1 Y2 Y3 Y4 Y5 Y6 Y7 Y8 Y9 Y11 Y12 Y14 Y15 Y16 Y17 Y18 Y19 Y20 Y21; U7 A1 A2 A3 A4 A5 A6 B1 B2 B3 B4 B5 B6 C1 C2 C3 C4 C5 C6 D1 D2 D3 D4 D5 D6 E1 E2 E3 E4 E5 E6 F1 F2 F3 F4 F5 F6 G1 G2 G3 G4 G5 G6 H1 H2 H3 H4 H5 H6; U8 A1 A2 A3 A4 A5 A6 B1 B2 B3 B4 B5 B6 C1 C2 C3 C4 C5 C6 D1 D2 D3 D4 D5 D6 E1 E2 E3 E4 E5 E6 F1 F2 F3 F4 F5 F6 G1 G2 G3 G4 G5 G6 H1 H2 H3 H4 H5 H6; U9 A1 A2 A3 A4 A5 A6 B1 B2 B3 B4 B5 B6 C1 C2 C5 C6 D1 D2 D5 D6 E1 E2 E5 E6 F1 F2 F5 F6 G3; U10 A1 A2 A3 A4 A5 A6 B1 B2 B3 B4 B5 B6 C1 C2 C5 C6 D1 D2 D5 D6 E1 E2 E5 E6 F1 F2 F5 F6 G3; U11 1 5 8; U12 1 4 5 10 24 27 30 31 32 33 35 38 39 40 41 42 43 44 46 47 48 49 50 51; U13 1 2 3 4 6 8 11 12 13 14 16 17 19 20 21 23 24 25 26 28 29 30 31 33 35; U14 6 8; U15 4 5 6 7 8 11 12 13 15 16; U16 3 4 5 6 7 8 12 16; U17 1 7 8 9 10 12 14 15 20 22 24 25 31; U18 2 3 5 7 8 10 11 12 15 17 18 19 20 22 24 25 26 28 30 32; U19 1 2 4 5 6 7 9 11 13 15 16 19 20 21 23 24 25 26 29 30 31 32; U20 3 7 8 9 10 11 14 16 20 21 23 25 26 27 31 32; U21 2 3 5 6 7 8; U22 2 3 4 5 7; U23 2 3 5 6 7 8; U24 2 3 4 5 6 8; Y1 1

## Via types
v1: diameter 0.483, hole 0.254, TOP to BOTTOM, 66 vias
v2: diameter 0.305, hole 0.152, TOP to GND, 138 vias
v3: diameter 0.305, hole 0.152, VCC to BOTTOM, 187 vias

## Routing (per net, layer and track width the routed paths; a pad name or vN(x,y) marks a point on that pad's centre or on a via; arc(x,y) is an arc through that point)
GND: length 685.5
  TOP w0.15: C51.2 4.87,47.6 ; 4.87,47.6 3.92,46.65 v2(1.68,46.65) C2.2 ; 4.87,47.6 v2(8.17,47.6) 8.73,47.6 8.93,47.4 9.21,47.4 9.21,47.68 ; C7.2 v3(18.86,48.51) 19.95,47.43 23.87,47.43 v2(24.93,48.49) C12.2 ; v3(28.6,46.39) C8.2 ; C15.2 17.67,22.61 17.67,23.44 ; v2(27.92,42.08) 28.6,42.08 ; 28.6,42.08 30.47,42.08 v1(31.16,41.39) ; 28.6,42.08 C9.2 ; v2(35.21,52.5) 35.21,53.14 36.53,54.46 39.11,54.46 ; v2(1.68,29.63) C5.2 ; U12.26 39.11,54.46 ; 39.11,54.46 39.11,54.87 39.8,55.57 v2(40.87,55.57) ; 17.67,23.44 15.05,23.44 ; 17.67,23.44 21.4,23.44 21.53,23.32 21.53,23 21.92,22.61 C16.2 v3(23.43,22.61) ; 15.05,23.44 15.05,22.61 ; 15.05,23.44 11.09,23.44 v2(10.73,23.09) v3(10.73,22.61) C13.2 ; U18.13 19.86,50.34 v2(19.47,50.34) v2(15.08,50.34) ; U13.15 v2(20.49,68.13) v2(20.49,70.02) ; C18.2 41.3,17.6 41.1,17.4 38.25,17.4 ; C3.2 v2(1.68,43.09) ; U17.4 8.17,56.28 ; 8.17,56.28 U17.28 ; 8.17,56.28 U17.21 v2(15.22,56.28) ; v2(27.92,38.37) 28.4,38.37 28.6,38.17 C10.2 ; v2(35.75,65.08) 35.75,64.57 35.86,64.47 U12.45 ; U14.7 v2(23.43,17.91) 23.94,17.4 v2(27.12,17.4) 38.25,17.4 ; 9.21,47.68 v3(9.21,48.51) C19.2 ; 9.21,47.68 12.94,47.68 v3(13.78,48.51) C20.2 ; C6.2 1.68,34.36 1.88,34.56 v2(2.39,34.56) ; C57.2 30.99,65.41 30.99,65.71 31.19,65.91 32.95,65.91 v2(33,65.96) ; v1(28.08,29.46) 28.08,28.98 28.45,28.61 C11.2 28.75,28.61 29.7,27.67 29.75,27.67 v1(31.7,25.73) ; v2(28.18,56.28) U18.21 ; U2.1 v2(20.49,77.52) ; 15.05,22.61 C14.2 ; 15.05,22.61 15.05,21.93 15.49,21.49 15.49,21.01 v2(15.97,21.01) ; v2(33,65.96) 33.45,65.96 33.45,65.41 C58.2 ; v2(33,65.96) 33,69.59 31.09,71.49 v2(30.05,71.49) ; v2(37.15,46.99) C17.2 ; C4.2 v3(1.68,38.77) ; v2(29.22,48.54) v2(32.37,48.54) 33.34,48.54 34.16,49.36 34.16,49.38 34.63,49.85 v2(34.63,49.91) ; 38.25,17.4 U11.7 ; C1.2 28.6,33.95 v2(28.09,33.95) ; v2(30.95,54.27) v2(29.54,54.27)
  GND w0.15: 27.92,46.39 v3(28.6,46.39) ; 27.92,46.39 v2(27.92,42.08) v2(27.92,38.37) ; 27.92,46.39 27.92,48.49 ; 3.54,23.09 v2(10.73,23.09) ; 3.54,23.09 2.39,24.25 2.39,29.63 ; 3.54,23.09 v2(3.54,22.38) ; v2(40.87,60.12) v2(40.87,55.57) ; v2(15.08,50.34) 14.49,49.76 13.78,49.76 ; 31.31,54.27 v2(31.31,63.83) 31.75,63.83 33,65.08 ; 31.31,54.27 32.35,53.22 v2(32.35,49.91) 32.37,49.89 v2(32.37,48.54) ; 31.31,54.27 v2(30.95,54.27) ; 18.81,63.74 15.55,63.74 15.29,63.48 v2(15.29,63.08) 15.25,63.04 15.25,56.32 v2(15.22,56.28) 14.29,56.28 11.69,53.68 11.69,51.54 13.46,49.76 13.78,49.76 ; 18.81,63.74 19.06,63.48 v2(19.06,60.12) ; 18.81,63.74 18.81,67.88 ; v2(35.21,52.5) 35.21,49.91 ; 35.21,49.91 35.21,48.93 v2(37.15,46.99) ; 35.21,49.91 v2(34.63,49.91) ; 13.78,49.76 v3(13.78,48.51) ; 2.39,29.63 v2(1.68,29.63) ; 2.39,29.63 v2(2.39,34.56) 2.39,35.87 1.68,36.58 v3(1.68,38.77) 1.32,39.13 1.32,42.74 v2(1.68,43.09) v2(1.68,46.65) ; v2(30.05,77.84) v2(30.05,71.49) ; v2(12.69,70.02) 14.83,67.88 18.81,67.88 ; 33,65.08 v2(33,65.96) ; 33,65.08 v2(35.75,65.08) ; 27.92,48.49 27.92,48.77 28.2,48.77 28.42,48.54 v2(29.22,48.54) ; 27.92,48.49 v2(24.93,48.49) ; v3(18.86,48.51) 19.47,49.12 v2(19.47,50.34) ; v2(20.49,70.02) v2(20.49,77.52) v2(9.09,77.52) ; v2(29.54,54.27) 29.54,56.28 ; 29.54,56.28 v2(28.18,56.28) ; 29.54,56.28 v2(29.54,58.17) ; v2(16.64,19.18) 15.97,19.85 v2(15.97,21.01) ; v2(8.17,47.6) v2(8.17,51.64) ; v2(27.12,17.4) v2(27.12,21.59) ; 18.81,67.88 19.06,68.13 v2(20.49,68.13) ; v2(23.43,17.91) v3(23.43,22.61) ; v2(28.09,33.95) 28.09,29.48 v1(28.08,29.46)
  VCC w0.15: 23.43,21.36 v3(23.43,22.61) ; 23.43,21.36 25.65,21.36 v3(27.46,19.56) 27.46,18.03 ; 23.43,21.36 v3(19.14,21.36) 15.05,21.36 ; 34.81,60.58 30.96,60.58 ; 34.81,60.58 36.27,59.11 v3(39.45,59.11) ; 34.81,60.58 v3(34.81,62.15) ; 30.96,60.58 v3(30.96,59.11) v3(30.96,55.91) v3(34.01,55.91) ; 30.96,60.58 v3(28.75,60.58) v3(25.93,60.58) 24.78,59.42 v3(22.82,59.42) ; v3(17.14,36.56) v3(15.14,36.56) 13.81,36.56 ; 15.05,21.36 v3(15.05,23.16) ; 15.05,21.36 11.98,21.36 v3(10.73,22.61) ; v3(9.21,48.51) v3(13.78,48.51) ; v3(13.78,48.51) 13.78,44.98 ; v3(13.78,48.51) v3(18.86,48.51) ; 37.4,41.57 v3(37.4,47.05) 28.6,47.05 ; 37.4,41.57 37.4,41.29 37.13,41.29 37.03,41.39 v3(36.21,41.39) ; 37.4,41.57 v3(41.05,41.57) 41.05,36.14 41.49,35.69 ; 13.78,44.98 13.78,44.64 12.7,43.56 v3(12.14,43.56) ; 13.78,44.98 14.72,44.98 v3(16.14,43.56) v3(20.14,43.56) 21.14,43.56 22.14,42.56 v3(23.14,42.56) ; v3(31.8,73.6) 32.61,72.79 v3(35.64,72.79) ; 13.81,34.56 v3(15.14,34.56) v3(17.14,34.56) ; 13.81,34.56 11.68,34.56 v3(10.68,33.56) ; 13.81,34.56 13.81,36.56 ; v3(13.14,28.56) 14.5,27.2 v3(17.67,27.2) ; v3(13.14,36.56) 13.81,36.56 ; 27.46,18.03 v3(32.5,18.03) ; 27.46,18.03 v3(27.46,16.51) ; v3(27.15,70.39) 26.72,70.39 25.7,71.41 v3(25.7,71.8) ; 41.49,35.69 41.49,31.85 v3(41.43,31.79) ; 41.49,35.69 v3(41.53,35.69) ; v3(25.21,48.01) 26.16,47.05 28.6,47.05 ; 28.6,47.05 v3(28.6,46.39) ; v3(7.14,40.56) 7.14,40.13 6.57,39.56 v3(6.14,39.56) v3(2.59,39.56) ; v3(8.79,61.85) 12.43,61.85 v3(13.45,62.87) ; v3(27.08,32.75) 24.05,32.75 v3(23.6,33.2) ; v3(24.36,71.8) v3(15.72,71.8) ; v3(1.68,30.49) v3(1.68,34.2) v3(1.68,38.77)
  BOTTOM w0.15: C2.2 1.83,45.89 2.59,45.12 2.59,42.33 ; U6.K3 23.6,36.56 ; 23.6,36.56 v3(23.6,33.2) 23.52,33.13 23.14,33.13 U6.P3 ; 23.6,36.56 23.6,42.1 v3(23.14,42.56) ; 2.59,42.33 C3.2 ; 2.59,42.33 v3(2.59,39.56) 2.59,39.17 2.2,38.77 v3(1.68,38.77) C4.2 ; C8.2 v3(28.6,46.39) 29.44,45.56 29.44,42.08 ; U22.1 9.31,54.34 ; 9.31,54.34 9.03,54.34 9.03,54.06 9.21,53.89 v3(9.21,48.51) C19.2 ; 9.31,54.34 9.31,59.42 ; 29.44,42.08 29.44,41.39 ; 29.44,42.08 28.6,42.08 C9.2 ; v3(10.73,22.61) C13.2 ; 7.61,34.56 7.61,33.18 7.68,33.1 ; 7.61,34.56 7.61,40.56 ; 7.61,34.56 U6.M19 ; 30.77,70.39 30.77,68.96 31,68.73 U20.13 ; 30.77,70.39 30.77,71.68 31.8,72.71 v3(31.8,73.6) U20.29 ; 30.77,70.39 28.19,70.39 ; 35.45,25.73 35.45,24.97 36.13,24.28 C37.2 ; 35.45,25.73 v1(31.7,25.73) ; 35.45,25.73 36.21,26.49 36.21,28.98 U10.F3 U10.F4 ; 7.61,40.56 7.65,40.6 7.65,42.71 8.04,43.1 9.14,43.1 ; 7.61,40.56 v3(7.14,40.56) ; v3(19.14,21.36) 19.14,22.61 C15.2 18.35,22.76 17.67,23.44 v3(17.67,27.2) 17.67,27.72 17.99,28.04 18.62,28.04 U6.V7 ; C10.2 28.6,36.56 29.41,36.56 ; 7.68,33.1 8.68,33.1 U6.N17 v3(10.68,33.56) 11.68,34.56 12.68,34.56 ; 7.68,33.1 7.68,30.02 U6.U18 ; v3(8.79,61.85) 9.3,61.85 9.31,61.84 9.31,59.42 ; 28.19,70.39 v3(27.15,70.39) ; 28.19,70.39 28.19,61.14 v3(28.75,60.58) ; 29.41,36.56 29.41,34.65 28.91,34.15 28.88,34.15 28.6,33.87 ; 29.41,36.56 29.69,36.84 29.69,40.04 29.44,40.29 29.44,41.39 ; C45.2 v3(13.45,62.87) ; v3(34.01,55.91) U19.14 34.01,50.84 36.04,48.81 36.09,48.81 36.09,47.5 37.4,47.5 v3(37.4,47.05) ; C48.2 41.81,41.95 41.43,41.57 v3(41.05,41.57) C49.2 ; C11.2 28.45,28.61 28.08,28.98 v1(28.08,29.46) 27.08,30.47 v3(27.08,32.75) 28.2,33.87 28.6,33.87 ; 28.6,33.87 C1.2 ; C6.2 v3(1.68,34.2) ; U21.1 9.31,59.42 ; 29.44,41.39 v1(31.16,41.39) ; 36.21,31.96 36.21,39.14 U9.F3 U9.F4 ; 36.21,31.96 36.21,31.23 U10.D3 U10.D4 ; 36.21,31.96 39.84,31.96 40,31.79 v3(41.43,31.79) 41.43,30.9 C46.2 ; U9.D4 U9.D3 v3(36.21,41.39) ; v3(15.05,23.16) 15.05,22.61 C14.2 ; v3(41.53,35.69) 42.01,35.69 C47.2 ; 12.68,34.56 U6.M13 ; 12.68,34.56 12.68,29.02 v3(13.14,28.56) ; C5.2 v3(1.68,30.49) ; v3(12.14,43.56) 11.68,43.1 9.14,43.1 ; v3(25.21,48.01) C27.2 ; v3(24.36,71.8) v3(25.7,71.8) ; C20.2 v3(13.78,48.51) ; v3(32.5,18.03) C50.2 ; 9.14,43.1 U6.C17 ; U24.1 22.4,54.34 22.82,54.76 v3(22.82,59.42) U23.1 ; C7.2 v3(18.86,48.51) ; v3(23.43,22.61) C16.2
VCC: length 681.9
  TOP w0.15: 30.57,49.45 30.57,49.76 ; 30.57,49.45 30.57,49.18 30.29,49.18 29.84,49.63 28.22,49.63 27.94,49.35 ; 30.57,49.45 33.29,49.45 v2(33.75,49.91) ; 30.57,49.76 v2(30.57,49.91) ; 30.57,49.76 31.37,49.76 31.46,49.85 C60.1 ; C15.1 v3(15.74,22.61) 16.75,21.59 20.05,21.59 ; v2(2.66,22.38) 3.11,21.92 6.35,21.92 ; 20.05,21.59 v3(20.05,22.61) C16.1 ; 20.05,21.59 25.11,21.59 ; 20.05,21.59 v1(20.05,20.17) ; v2(29.56,38.7) v3(28.6,38.7) C9.1 ; C19.1 v3(5.83,48.51) 7.07,49.76 v2(10.4,49.76) ; 11.42,21.64 11.42,22.35 11.68,22.61 C14.1 ; 11.42,21.64 6.63,21.64 6.35,21.92 ; 11.42,21.64 12.06,21.01 v2(15.08,21.01) ; 14.58,49.76 14.58,50.34 C52.1 ; 14.58,49.76 14.58,49.35 ; 14.58,49.76 v2(10.4,49.76) ; 20.66,49.35 v2(20.66,51.64) ; 20.66,49.35 14.58,49.35 ; 20.66,49.35 27.94,49.35 ; 20.66,49.35 21.52,48.49 C12.1 ; 14.58,49.35 15.42,48.51 C7.1 ; C54.1 28.34,48.6 27.94,49 27.94,49.35 ; C13.1 7.03,22.61 6.35,21.92 ; U2.8 26.04,73.61 26.24,73.42 26.24,73.12 26.04,72.92 18.62,72.92 18.24,73.3 18.24,73.61 ; v2(38.46,54.13) U12.25 38.46,51.44 37.95,50.93 v2(34.56,50.93) ; C17.1 v2(33.77,46.99) ; 25.11,21.59 C56.1 ; 25.11,21.59 27.21,19.48 v2(29.71,19.48) ; 9.09,74.92 10.5,74.92 11.39,74.03 v2(11.39,73.61) U1.8 v2(17.24,73.61) 18.24,73.61 ; v2(2.47,36.92) 1.68,36.92 C4.1 v2(1.68,35.39) ; 36.73,9.79 v2(36.73,7.05) ; 36.73,9.79 37.62,9.79 41.3,13.48 C18.1 ; 36.73,9.79 34.79,9.79 33.35,11.24 Y1.4 v2(29.71,11.24) ; v2(13.99,63.08) 13.99,63.77 14.42,64.2 v2(19.89,64.2) ; v2(10.4,49.76) 10.4,48.51 C20.1 ; v1(27.6,34.63) v3(28.6,34.63) C10.1 ; C2.1 v2(2.78,44.03) ; 18.24,73.61 18.24,74.54 18.62,74.92 19.25,74.92 ; v1(28.35,25.47) 28.35,26.66 28.45,26.76 C11.1 ; C1.1 v2(28.6,30.57) 28.67,30.51 v1(28.67,29.56) ; U17.27 v2(8.97,61.41) ; C3.1 v3(1.68,39.71) ; C5.1 v2(1.68,26.25) ; v2(30.16,43.01) 29.52,43.01 28.75,43.78 C8.1 ; C6.1 v2(1.68,30.82) ; U17.19 v2(10.4,54.68) ; U12.12 v2(30.92,54.92)
  GND w0.15: 2.47,39.71 v2(2.47,36.92) ; 2.47,39.71 v3(1.68,39.71) ; 2.47,39.71 2.78,40.03 v2(2.78,44.03) 2.78,47.77 3.53,48.51 ; 11.39,63.08 9.72,61.41 v2(8.97,61.41) ; 11.39,63.08 v2(11.39,70.02) v2(11.39,73.61) ; 11.39,63.08 v2(13.99,63.08) ; v2(36.48,3.05) 36.73,3.3 v2(36.73,7.05) ; v2(20.66,51.64) v2(20.66,60.12) 20.66,63.08 ; 40.26,54.92 39.48,54.13 v2(38.46,54.13) ; 40.26,54.92 40.26,60.16 v2(40.87,60.77) ; 40.26,54.92 v2(40.87,54.92) ; v2(35.79,75.89) v2(35.79,73.29) v2(35.79,70.19) v2(35.79,66.94) 33.49,66.94 32.48,65.92 v2(32.48,65.41) v2(30.57,65.41) 30.57,58.82 ; 20.66,63.08 v2(22.44,63.08) ; 20.66,63.08 20.33,63.08 19.89,63.53 v2(19.89,64.2) ; 3.53,48.51 v2(3.53,55.48) ; 3.53,48.51 v3(5.83,48.51) ; 30.57,58.82 v2(29.54,58.82) ; 30.57,58.82 30.57,54.92 ; v2(34.56,52.5) v2(34.56,50.93) 34.14,50.93 33.75,50.53 v2(33.75,49.91) 33.75,47.02 v2(33.77,46.99) ; v2(17.24,73.61) v2(17.24,70.02) ; 30.57,54.92 v2(30.92,54.92) ; 30.57,54.92 v2(30.57,49.91) 30.16,49.5 v2(30.16,43.01) 30.16,39.29 v2(29.56,38.7) 29.56,35.59 v3(28.6,34.63) v2(28.6,30.57) ; v2(2.66,22.38) 1.68,23.36 v2(1.68,26.25) 1.32,26.61 1.32,30.47 v2(1.68,30.82) v2(1.68,35.39) ; v2(29.71,11.24) v2(29.71,19.48) 30.13,19.48 30.63,19.99 v2(30.63,20.62) ; v2(15.08,21.01) 15.08,21.95 v3(15.74,22.61) ; v2(10.4,54.68) v2(10.4,49.76)
  VCC w0.15: 9.14,30.56 v3(9.14,31.56) 9.14,33.56 ; 9.14,30.56 v3(9.14,29.56) v3(10.14,29.56) v3(10.14,27.56) 10.14,23.21 ; 9.14,30.56 v3(8.14,30.56) ; 21.14,33.56 20.5,33.56 ; 21.14,33.56 v3(23.14,33.56) 23.14,34.63 ; 21.14,33.56 v3(21.14,34.56) ; 20.5,33.56 20.5,30.56 ; 20.5,33.56 v3(17.14,33.56) ; 10.4,48.87 9.06,48.87 8.7,48.51 8.14,48.51 ; 10.4,48.87 15.59,48.87 ; 10.4,48.87 v3(10.4,49.47) ; v3(21.83,48.01) 20.97,48.87 15.59,48.87 ; 14.14,42.56 v3(14.14,44.56) ; 14.14,42.56 v3(12.14,42.56) 10.14,42.56 ; 14.14,42.56 v3(16.14,42.56) v3(20.14,42.56) 20.14,42.13 20.71,41.56 21.14,41.56 ; 35.83,40.66 35.5,40.66 34.71,41.46 v3(34.71,42.14) ; 35.83,40.66 v3(35.83,40.27) ; 35.83,40.66 v3(39.92,40.66) ; 35.88,21.4 v3(36.73,21.4) ; 35.88,21.4 v3(35.88,18.59) ; 35.88,21.4 v3(34.19,21.4) 33.52,21.4 ; v3(31.65,21.4) 33.52,21.4 ; 33.52,21.4 33.52,23.2 ; 9.14,33.56 v3(9.14,35.56) v3(13.14,35.56) ; 9.14,33.56 8.14,33.56 ; 15.59,48.87 v3(15.59,49.75) ; 2.03,39.71 v3(1.68,39.71) ; 2.03,39.71 2.03,42.31 ; 2.03,39.71 v3(2.03,35.39) ; 8.14,33.56 v3(7.14,33.56) ; 8.14,33.56 v3(8.14,34.56) ; v3(20.14,28.56) 20.5,28.92 20.5,30.56 ; 2.03,42.31 4.85,42.31 5.1,42.56 v3(6.14,42.56) 8.14,42.56 ; 2.03,42.31 2.03,42.91 v3(1.68,43.27) ; 21.14,41.56 v3(23.14,41.56) 23.14,41.13 23.71,40.56 v3(24.14,40.56) ; 21.14,41.56 v3(21.14,39.56) ; 28.14,34.63 v1(27.6,34.63) 24.14,34.63 ; 28.14,34.63 v3(28.6,34.63) ; 28.14,34.63 28.14,38.7 ; v3(13.14,37.56) v3(14.14,37.56) v3(15.14,37.56) v3(16.14,37.56) ; 33.52,23.2 v3(29.52,23.2) ; 33.52,23.2 v3(33.52,24.13) ; 10.14,42.56 v3(9.14,42.56) 8.14,42.56 ; 10.14,42.56 v3(10.14,43.56) ; 20.05,17.02 24.16,17.02 ; 20.05,17.02 v1(20.05,20.17) ; 20.05,17.02 v3(18.76,17.02) ; 24.16,17.02 v3(24.16,16.51) ; 24.16,17.02 v3(24.16,19.56) ; 24.14,34.63 v3(24.14,35.56) ; 24.14,34.63 23.14,34.63 ; 8.14,48.51 v3(8.14,43.56) 8.14,42.56 ; 8.14,48.51 v3(5.83,48.51) ; 10.14,23.21 7.96,23.21 v3(7.35,22.61) ; 10.14,23.21 10.93,23.21 11.21,23.49 11.67,23.49 ; v3(20.05,22.61) v3(15.74,22.61) 15.74,22.99 15.23,23.49 11.67,23.49 ; v3(13.14,29.56) 13.57,29.56 14.14,28.99 v3(14.14,28.56) ; 11.67,23.49 v3(11.67,22.61) ; 23.14,34.63 v3(23.14,37.56) ; v3(32.15,71.19) v3(27.15,71.19) ; 28.14,38.7 v3(28.14,42.47) ; 28.14,38.7 v3(28.6,38.7) ; v3(15.14,33.56) v3(14.14,33.56) v3(13.14,33.56) ; 20.5,30.56 v3(21.14,30.56) ; 35.88,16.32 v3(36.73,16.32) ; 35.88,16.32 v3(35.88,17.47) ; 35.88,16.32 v3(31.65,16.32) ; v3(25.93,63.88) 24.92,62.87 v3(16.83,62.87)
  BOTTOM w0.15: 16.02,49.75 16.73,49.04 16.73,48.51 C7.1 ; 16.02,49.75 16.02,53.51 16.35,53.84 ; 16.02,49.75 v3(15.59,49.75) ; U20.5 32.6,71.99 ; 32.6,71.99 U20.30 ; 32.6,71.99 32.15,71.54 v3(32.15,71.19) 31.8,70.84 U20.12 ; C46.1 41.3,29.8 ; 41.3,29.8 39.96,29.8 39.88,29.73 36.21,29.73 U10.E3 U10.E4 34.71,30.11 ; 41.3,29.8 41.67,29.8 42.11,30.24 42.11,32.78 C47.1 42.01,33.49 41.81,33.69 41.56,33.69 41.05,34.2 C49.1 40.9,38.95 39.92,39.93 v3(39.92,40.66) 39.92,45.16 40.36,45.61 40.9,45.61 41.66,44.84 C48.1 ; U23.10 16.35,59.42 ; 16.35,59.42 15.38,60.38 15.38,62.03 16.07,62.71 C45.1 v3(16.83,62.87) 16.83,66.74 17.98,67.9 U4.8 ; 16.35,59.42 16.35,58.92 ; 4.99,54.34 4.99,53.84 ; 4.99,54.34 4.99,58.92 ; 4.99,54.34 U22.10 ; 4.99,53.84 4.99,49.35 v3(5.83,48.51) C19.1 ; 4.99,53.84 U22.9 ; 6.6,38.56 U6.H20 ; 6.6,38.56 U6.H19 ; 6.6,38.56 6.6,39.56 ; C15.1 v3(15.74,22.61) ; U6.K12 U6.L12 U6.M12 v3(14.14,33.56) ; v3(13.14,29.56) v3(13.14,33.56) ; U23.9 16.35,58.92 ; 16.35,58.92 16.35,54.34 ; 16.35,54.34 16.35,53.84 ; 16.35,54.34 U24.10 ; 16.35,53.84 U24.9 ; C13.1 v3(7.35,22.61) ; C6.1 1.68,30.9 2.49,30.9 ; C38.1 34.79,47.35 34.71,47.27 v3(34.71,42.14) U9.C4 U9.C3 ; U9.E4 v3(35.83,40.27) ; 28.67,30.42 28.6,30.48 C1.1 ; 28.67,30.42 v1(28.67,29.56) ; 28.67,30.42 29.2,30.42 29.52,30.1 29.52,29.75 ; 6.6,39.56 6.6,42.1 v3(6.14,42.56) ; 6.6,39.56 U6.G19 ; v3(21.14,39.56) 21.6,39.1 21.6,38.46 22.04,38.02 22.68,38.02 v3(23.14,37.56) ; C27.1 v3(21.83,48.01) ; C11.1 28.45,26.76 28.35,26.66 28.35,26 ; C2.1 v3(1.68,43.27) ; 29.52,29.75 34.71,29.75 34.71,30.11 ; 29.52,29.75 29.52,26 ; U6.L9 U6.L10 ; U6.L10 U6.L11 ; U6.L10 U6.M10 U6.N10 ; U6.L10 U6.K10 v3(16.14,37.56) U6.J9 ; v1(20.05,20.17) v3(20.05,22.61) C16.1 ; 2.49,30.9 2.77,31.18 2.77,34.66 v3(2.03,35.39) 1.83,35.39 1.68,35.55 C4.1 ; 2.49,30.9 2.49,28.27 1.68,27.46 C5.1 ; C8.1 28.6,42.93 v3(28.14,42.47) ; U21.9 4.99,58.92 ; 4.99,58.92 4.99,59.42 U21.10 6.58,59.42 7.15,59.99 7.15,62.53 7.66,63.04 8,63.04 8.79,63.83 C41.1 8.79,67.34 9.35,67.9 U3.8 ; C3.1 v3(1.68,39.71) ; C37.1 v3(33.52,24.13) ; U6.N10 v3(15.14,33.56) ; U6.N10 v3(17.14,33.56) ; 35.12,18.03 35.88,18.03 ; 35.88,18.03 v3(35.88,18.59) ; 35.88,18.03 v3(35.88,17.47) ; C20.1 10.4,48.51 v3(10.4,49.47) ; C14.1 v3(11.67,22.61) ; v3(25.93,63.88) 25.93,70.56 26.57,71.19 v3(27.15,71.19) ; 28.35,26 29.52,26 ; 28.35,26 v1(28.35,25.47) ; 29.52,26 v3(29.52,23.2) ; C10.1 v3(28.6,34.63) ; 34.71,30.11 34.71,31.23 U10.C4 U10.C3 ; C9.1 v3(28.6,38.7)
A1: length 16.1
  GND w0.15: v1(31.31,44.56) v2(31.31,52.5)
  VCC w0.15: v1(31.31,44.56) v3(23.14,44.56)
A2: length 17.8
  GND w0.15: v1(31.96,43.56) v2(31.96,52.5)
  VCC w0.15: v1(31.96,43.56) v3(23.14,43.56)
A3: length 16
  TOP w0.15: U12.16 32.61,51.87 31.92,51.18 v1(23.14,51.18)
  VCC w0.15: v1(23.14,51.18) v3(23.14,45.56)
A4: length 19.8
  GND w0.15: v1(33.26,43.98) v2(33.26,52.5)
  VCC w0.15: v3(22.14,43.56) 22.56,43.98 v1(33.26,43.98)
A5: length 20.6
  TOP w0.15: U12.18 33.91,51.87 32.8,50.76 v1(23.57,50.76)
  BOTTOM w0.15: v1(23.57,50.76) 23.57,43.33 23.25,43.02 22.6,43.02 U6.D4
A6: length 22.6
  TOP w0.15: v1(21.5,50.34) 33.29,50.34 34.21,51.26 35.25,51.26 35.86,51.87 U12.21
  BOTTOM w0.15: U6.C5 21.6,44.02 21.6,46.69 21.5,46.78 v1(21.5,50.34)
A7: length 22.1
  TOP w0.15: v1(37.7,51.35) 37.16,51.35 U12.23
  VCC w0.15: v3(21.14,44.56) 21.75,45.17 23.54,45.17 24.24,45.86 24.24,47.54 28.05,51.35 v1(37.7,51.35)
ADDR0: length 29
  VCC w0.15: v3(21.14,28.56) 21.72,27.98 21.72,27.93 23.18,26.47 35.2,26.47 v3(36.58,27.85) 37.84,27.85 38.04,28.05 38.04,36.56 v3(36.58,38.01)
ADDR1: length 20.4
  VCC w0.15: v3(24.14,29.56) 24.65,29.05 32.86,29.05 ; v3(33.21,27.48) 32.86,27.83 32.86,29.05 ; v3(33.21,37.64) 32.86,37.29 32.86,29.05
  BOTTOM w0.15: U9.H6 v3(33.21,37.64) ; U10.H6 v3(33.21,27.48)
ADDR2: length 30.6
  VCC w0.15: v3(24.14,30.56) 23.79,30.21 23.01,30.21 22.81,30.4 22.81,30.79 23.21,31.19 24.39,31.19 24.77,30.81 24.77,30.43 24.97,30.23 26.55,30.23 31.7,35.37 31.7,37.57 33.22,39.09 33.76,39.09 33.96,38.9 v3(33.96,37.64) 33.96,28.23 v3(34.33,27.85)
  BOTTOM w0.15: U9.H5 v3(33.96,37.64)
ADDR3: length 26.9
  VCC w0.15: v3(33.58,38.77) 33.56,38.74 33.56,38.04 ; v3(33.21,28.23) 33.56,28.58 33.56,38.04 ; 33.56,38.04 33.09,38.04 32.2,37.15 32.2,35.12 27.06,29.98 24.85,29.98 24.47,30.36 24.47,30.7 24.28,30.89 23.89,30.89 23.56,30.56 v3(23.14,30.56)
  BOTTOM w0.15: U10.G6 v3(33.21,28.23)
ADDR4: length 10.2
  VCC w0.15: v3(34.33,28.61) v3(34.33,38.77)
  vias: v3(23.14,29.56)
ADDR5: length 26.1
  VCC w0.15: v3(22.14,30.56) 22.49,30.21 22.49,29.69 25.03,27.15 34.16,27.15 34.73,27.72 34.73,28.61 ; 34.73,28.61 v3(35.09,28.61) ; 34.73,28.61 34.73,38.41 v3(35.09,38.77)
ADDR6: length 10.5
  VCC w0.15: v3(35.09,38.01) 35.09,31.38 35.44,31.02 35.44,28.21 v3(35.09,27.85)
  vias: v3(22.14,29.56)
ADDR7: length 26.1
  VCC w0.15: v3(22.14,28.56) 23.8,26.9 34.88,26.9 v3(35.83,27.85) 36.26,28.28 36.72,28.28 36.91,28.47 36.91,34.46 35.83,35.54 v3(35.83,38.01)
ADDR8: length 27.4
  VCC w0.15: 35.51,38.77 v3(36.58,38.77) ; 35.51,38.77 35.43,38.69 35.43,34.32 36.58,33.16 v3(36.58,28.61) ; 35.51,38.77 35.51,39.24 34.34,39.24 34.19,39.4 33.11,39.4 31.4,37.68 31.4,35.77 26.19,30.56 v3(25.14,30.56)
ADDR9: length 37.3
  VCC w0.15: 37.87,38.01 v3(37.33,38.01) ; 37.87,38.01 37.87,38.71 36.72,39.85 34.94,39.85 34.79,40 32.8,40 29.43,36.64 29.43,34.58 27.02,32.17 21.21,32.17 20.81,31.77 20.81,31.4 21.01,31.21 21.79,31.21 v3(22.14,31.56) ; 37.87,38.01 38.54,37.34 38.54,27.92 38.1,27.48 v3(37.71,27.48)
  BOTTOM w0.15: U10.H1 v3(37.71,27.48)
ADDR10: length 33.4
  VCC w0.15: 36.91,38.77 36.91,38.45 36.81,38.34 36.45,38.34 36.26,38.15 36.26,36.73 37.71,35.28 v3(37.71,28.23) ; 36.91,38.77 v3(37.33,38.77) ; 36.91,38.77 36.91,39.1 36.47,39.55 34.64,39.55 34.49,39.7 33.05,39.7 30.19,36.84 30.19,34.96 27.14,31.91 21.49,31.91 v3(21.14,31.56)
  BOTTOM w0.15: U10.G1 v3(37.71,28.23)
HDI_STACK: length 30.1
  TOP w0.15: v1(31.3,70.19) U15.3 28.2,70.19 27.34,71.05 v1(23.18,71.05) 22.51,71.72 15.01,71.72 13.99,70.7 U13.32 13.99,69.33 13.21,68.55 v1(11.81,68.55)
  VCC w0.15: v3(35.64,71.19) 34.64,70.19 v1(31.3,70.19)
  BOTTOM w0.15: v1(23.18,71.05) 24.36,71.05 U4.2 ; U3.9 v1(11.81,68.55)
NET1: length 5.8
  TOP w0.15: U1.9 v1(16.07,74.27)
  BOTTOM w0.15: v1(16.07,74.27) 17.6,72.73 17.6,71.53 17.98,71.15 U4.13
NET2: length 7.6
  TOP w0.15: 14.84,74.92 v1(16.02,74.92)
  BOTTOM w0.15: v1(16.02,74.92) 15.4,74.3 15.4,73.81 17.28,71.93 17.28,71.21 17.98,70.5 U4.12
NET3: length 9.8
  TOP w0.15: v1(16.02,75.98) 16.02,75.81 15.77,75.56 U1.11
  BOTTOM w0.15: U4.11 17.98,69.85 16.97,70.86 16.97,71.8 15.1,73.68 15.1,75.06 v1(16.02,75.98)
NET4: length 38
  TOP w0.15: U17.6 v1(7.09,54.68) ; U12.9 v1(26.36,56.87) ; U18.6 v1(13.31,54.68)
  GND w0.15: v1(7.09,54.68) 7.14,54.64 v1(7.14,46.21)
  VCC w0.15: v1(26.36,56.87) 24.18,54.68 v1(13.31,54.68) v1(7.09,54.68)
  BOTTOM w0.15: U6.A19 v1(7.14,46.21)
NET5: length 32
  TOP w0.15: 26.82,13.77 31.4,13.77 31.9,14.27 v2(31.9,14.94) ; 26.82,13.77 D1.2 ; 26.82,13.77 25.76,14.83 20,14.83 16.93,17.91 U14.2
  GND w0.15: v2(31.9,14.94) v2(31.9,3.05)
NET7: length 13.7
  TOP w0.15: U14.3 17.25,16.64 19.55,14.33 23.34,14.33 25.88,11.79 D1.1
NET8: length 77.8
  TOP w0.15: v1(23.84,73.59) 23.84,74.16 23.95,74.27 U2.9 ; U12.11 28.91,55.57 28.36,55.02 v1(28.36,53.83) 27.2,52.67 16.76,52.67 ; U18.9 16.66,52.22 16.76,52.33 16.76,52.67 ; 16.76,52.67 v1(16.76,56.77) ; v1(7.51,58.88) 6.77,58.88 6.57,59.08 U17.30
  GND w0.15: v1(28.59,73.59) 28.59,72.3 v2(30.05,70.84) 30.6,70.29 v1(30.6,66.41)
  VCC w0.15: v1(7.51,58.88) 7.51,57.98 8.72,56.77 v1(16.76,56.77) ; v3(11.52,74.93) 12.86,73.59 v1(23.84,73.59)
  BOTTOM w0.15: v1(28.36,53.83) 29.92,55.4 29.92,62.88 30.6,63.56 ; 30.6,63.56 v1(30.6,66.41) ; 30.6,63.56 33.18,63.56 34.01,62.74 U19.27 ; v1(28.59,73.59) U20.22 v1(23.84,73.59)
NET9: length 42.7
  TOP w0.15: U17.2 v2(6.4,57.88) ; U15.10 35.16,67.59 33.96,66.4 33.96,65.3 33.58,64.92 31.15,64.92 30.9,64.67 30.9,58.24 30.18,57.52 U12.8 26.36,57.52 24.74,59.14 22.69,59.14 22.63,59.08 19.37,59.08 18.97,58.68 U18.1 14.12,58.68 13.66,59.14 11.17,59.14 10.98,58.94 10.98,58.42 v2(10.43,57.88)
  GND w0.15: v2(10.43,57.88) v2(6.4,57.88)
NET11: length 12.5
  TOP w0.15: U16.15 33.89,77.19 32.88,78.19 v2(25,78.19)
  GND w0.15: v2(25,78.19) v2(25,76.86)
NET12: length 32.6
  VCC w0.15: 18.62,70.5 v3(24.36,70.5) 24.97,71.11 24.97,71.53 27.82,74.39 v3(35.64,74.39) ; 18.62,70.5 v3(18.62,68.55) ; 18.62,70.5 11.52,70.5 ; v3(9.98,70.5) 11.52,70.5 ; 11.52,70.5 v3(11.52,73.66)
NET13: length 36.9
  TOP w0.15: U17.23 13.21,57.88 13.45,58.12 v1(13.45,58.34) ; U18.23 20.7,57.88 v1(20.24,58.34) ; v1(31.78,62.01) 38.63,62.01 39.14,61.51 39.14,59.91 40.24,58.82 U12.34
  VCC w0.15: v1(31.78,62.01) 23.41,62.01 20.24,58.84 v1(20.24,58.34) v1(13.45,58.34)
NET14: length 40.6
  VCC w0.15: v3(8.1,57.92) v3(10.35,57.92) v3(20.74,57.92) 27.33,57.92 29.78,55.47 39.09,55.47 v3(39.45,55.11)
  BOTTOM w0.15: v3(8.1,57.92) 8.1,53.48 6.96,52.34 U22.6 ; U23.4 v3(20.74,57.92)
NET15: length 27.3
  VCC w0.15: v3(7,53.34) 16.35,53.34 ; 16.35,53.34 29.19,53.34 v3(30.96,55.11) ; 16.35,53.34 v3(16.35,52.84)
  BOTTOM w0.15: U22.8 v3(7,53.34) ; U24.7 v3(16.35,52.84)
